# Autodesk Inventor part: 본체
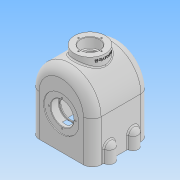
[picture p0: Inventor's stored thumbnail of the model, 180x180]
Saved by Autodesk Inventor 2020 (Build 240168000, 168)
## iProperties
Created: 2023-03
Part Number: 본체
Material: 일반
Document SubType Name: Modeling
Designer: user
Density: 1 g/cm^3
Appearance: 기본값
Author: user
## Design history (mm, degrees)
sketch "스케치1"
  geometry: L1 (-70, 94)-(70, 94); L2 (70, 94)-(70, 0); L3 (70, 0)-(-70, 0); L4 (-70, 0)-(-70, 94); L5 (-60, 94)-(-60, 0); L6 (60, 0)-(60, 94); A1 r 70 centre (0, 94) between (70, 94) and (-70, 94); A2 r 60 centre (0, 94) between (60, 94) and (-60, 94); 2 further points
  constraints: 12 end point, 4 point on circle, 3 parallel, 2 centre point, 2 midpoint, 2 point on line, 1 coincident, 1 horizontal, 1 perpendicular
  dimensions: "d1" = 94 distance of L3.end L1.start; "d2" = 140 distance of L2.end L3.end; "d3" = 10 radial gap between concentric circles of A1 A2; "d4" = 10 distance between parallel lines of L5 L4; "d5" = 10 distance between parallel lines of L2 L6
extrude "돌출1" new body sketch "스케치1" stored distance "d6" = 130; taper "d7" = 0 deg
sketch "스케치2"
  geometry: L1 (-60, 0)-(-60, 94) reference; L2 (60, 94)-(60, 0) reference; L3 (-70, 0)-(-70, 94) reference; L4 (70, 94)-(70, 0) reference; L5 (70, 0)-(60, 0) reference; L6 (60, 0)-(60, 94) reference; L7 (-60, 94)-(-60, 0) reference; L8 (-60, 0)-(-70, 0) reference; L9 (-60, 0)-(60, 0); A1 r 60 centre (0, 94) between (60, 94) and (-60, 94) reference; A2 r 70 centre (0, 94) between (70, 94) and (-70, 94) reference; A3 r 60 centre (0, 94) between (60, 94) and (-60, 94) reference; 1 further point
  constraints: 2 end point, 1 horizontal
extrude "돌출2" join sketch "스케치2" distance "d8" = 10; taper "d9" = 0 deg
sketch "스케치6"
  geometry: L1 (154, 55)-(0, 55) reference; L2 (0, 55)-(0, 65) reference; L3 (0, 65)-(164, 65) reference; L4 (164, 65)-(164, -65) reference; L5 (154, -55)-(154, 55) reference; L6 (164, -65)-(0, -65) reference; L7 (0, -65)-(0, -55) reference; L8 (0, -55)-(154, -55) reference; L9 (117, 65)-(117, 55); L10 (154, 55)-(94, 55) reference; L11 (117, 55)-(105.879, 43.879); L12 (103.757, 43)-(75, 43); L13 (75, 43)-(75, 65); L14 (75, 65)-(117, 65); A1 r 3 centre (103.757, 46) between (103.757, 43) and (105.879, 43.879); 3 further points
  constraints: 10 end point, 4 perpendicular, 4 point on line, 2 point on circle, 2 tangent, 1 centre point, 1 horizontal alignment
  dimensions: "d29" = 135 deg angle of L10 L11; "d30" = 22 distance of L12.end L13.end; "d50" = 75 distance of L2.end L13.end; "d51" = 60 diameter of point (105, 43) L13; "d52" = 3 radius of A1
revolve "회전3" sketch "스케치6" stored, may be unused: angle "d34" = 90 deg
sketch "스케치7"
  geometry: L1 (-70, 0)-(70, 0) reference; L2 (-70, 0)-(-70, 94) reference; L3 (70, 94)-(70, 0) reference; L4 (70, 0)-(-70, 0) reference; L5 (-70, 0)-(-70, 94) reference; L6 (70, 94)-(70, 0) reference; L7 (70, 0)-(-70, 0) reference; A1 r 70 centre (0, 94) between (70, 94) and (-70, 94) reference; A2 r 70 centre (0, 94) between (70, 94) and (-70, 94) reference; A3 r 70 centre (0, 94) between (70, 94) and (-70, 94) reference; 2 further points
  constraints: 1 vertical alignment
  dimensions: "d35" = 75 distance from line of L1 point (0, 75)
hole "구멍2" sketch "스케치7" at (0, 75) diameter "d36" = 52; stored, may be unused: countersink angle "d40" = 60 deg, drill point angle "d42" = 0 deg; dims "d37" = 6, "d38" = 80, "d39" = 2, "d41" = 18
sketch "스케치8"
  geometry: C1 r 26 at (0, 0) reference; 1 further point
hole "구멍3" sketch "스케치8" at (0, 0) diameter "d43" = 46; stored, may be unused: countersink angle "d47" = 60 deg, drill point angle "d49" = 0 deg; dims "d44" = 6, "d45" = 43, "d46" = 22, "d48" = 5
fillet "모깎기1" dims "d53" = 1
sketch "스케치9" dims "d54" = 60
  geometry: L1 (0, 0)-(0, 30); C1 r 26 at (0, 0) reference; 2 further points
  constraints: 2 coincident, 2 end point, 1 vertical, 1 vertical alignment, 2 other
hole "구멍4" sketch "스케치9" at (0, 30) diameter "d55" = 3.242; stored, may be unused: countersink angle "d59" = 60 deg, drill point angle "d61" = 118 deg; dims "d56" = 8, "d57" = 43, "d58" = 22, "d60" = 10
sketch "스케치12"
  geometry: L1 (140, 0)-(140, 130) reference; L2 (140, 104)-(140, 80); A1 r 12 centre (140, 92) between (140, 80) and (140, 104); 1 further point
  constraints: 3 point on line, 2 end point, 2 point on circle, 1 centre point
  dimensions: "d80" = 12 radius of A1; "d81" = 27 vertical distance of point (70, 65) A1.centre
extrude "돌출3" join sketch "스케치12" distance "d82" = 28; taper "d83" = 0 deg
node "작업 평면2"
sketch "스케치13"
  geometry: L1 (-70, 0)-(-70, 94) reference; L2 (70, 94)-(70, 28) reference; L3 (70, 28)-(82, 28) reference; L4 (82, 28)-(82, 0) reference; L5 (82, 0)-(60, 0) reference; L6 (60, 0)-(60, 94) reference; L7 (-60, 94)-(-60, 0) reference; L8 (-60, 0)-(-70, 0) reference; L9 (82, 28)-(70, 28) reference; L10 (70, 94)-(70, 0) reference; L11 (70, 40)-(70, 28); L12 (70, 28)-(82, 28); A1 r 60 centre (0, 94) between (60, 94) and (-60, 94) reference; A2 r 12 centre (70, 28) between (82, 28) and (70, 40); A3 r 70 centre (0, 94) between (70, 94) and (-70, 94) reference; 1 further point
  constraints: 4 end point, 2 point on circle, 1 centre point, 1 coincident, 1 collinear, 1 perpendicular, 1 point on line
revolve "회전4" sketch "스케치13" stored, may be unused: angle "d85" = 90 deg
sketch "스케치14"
  geometry: A1 r 12 centre (140, 92) between (140, 80) and (140, 104) reference; 1 further point
hole "구멍6" sketch "스케치14" at (140, 92) diameter "d86" = 10.106; stored, may be unused: countersink angle "d90" = 60 deg, drill point angle "d92" = 118 deg; dims "d87" = 24, "d88" = 43, "d89" = 22, "d91" = 26
fillet "모깎기2" dims "d93" = 20
fillet "모깎기3" dims "d94" = 3
node "작업 평면3"
sketch "스케치15"
  geometry: C1 r 35 at (0, 0); 1 further point
  constraints: 1 centre point, 1 coincident
  dimensions: "d96" = 70 diameter of C1
extrude "돌출4" join sketch "스케치15" stored distance "d97" = 28; taper "d98" = 0 deg
sketch "스케치16"
  geometry: C1 r 35 at (0, 0) reference
hole "구멍7" sketch "스케치16" at (0, 0) diameter "d99" = 34; stored, may be unused: countersink angle "d103" = 60 deg, drill point angle "d105" = 0 deg; dims "d100" = 24, "d101" = 43, "d102" = 22, "d104" = 26
sketch "스케치17" dims "d106" = 52
  geometry: L1 (0, 0)-(0, 26); C1 r 35 at (0, 0) reference; 1 further point
  constraints: 2 coincident, 2 end point, 1 vertical, 1 vertical alignment, 2 other
hole "구멍8" sketch "스케치17" at (0, 26) diameter "d107" = 3.242; stored, may be unused: countersink angle "d111" = 60 deg, drill point angle "d113" = 118 deg; dims "d108" = 8, "d109" = 43, "d110" = 22, "d112" = 10
fillet "모깎기4" dims "d117" = 3
chamfer "모따기1" distance "d118" = 1; stored, may be unused: second distance "d119" = 2, angle "d120" = 45 deg
fillet "모깎기5" dims "d121" = 10
node "작업 평면4"
sketch "스케치18"
  geometry: 1 further point
sketch "스케치19"
  geometry: L1 (1.739, 31.03)-(1.739, -31.03); L2 (1.739, -31.03)-(-17.739, -31.03); L3 (-17.739, -31.03)-(-17.739, 31.03); L4 (-17.739, 31.03)-(1.739, 31.03); L5 (-8, 31.03)-(-8, -31.03); L6 (-17.739, 0)-(1.739, 0); L7 (0, -35)-(0, 35) reference; 2 further points
  constraints: 5 midpoint, 4 end point, 1 horizontal alignment, 2 other
  dimensions: "d122" = 8 distance between parallel lines of L7 L5
feature "엠보싱2" sketch "스케치19" dims "d123" = 0.5, "d124" = 0
sketch "스케치20"
  geometry: L1 (100, 10)-(0, 10) reference; L2 (-10, 20)-(-10, 110) reference; L3 (100, 120)-(0, 120) reference; L4 (110, 20)-(110, 110) reference; A1 r 10 centre (0, 20) between (-10, 20) and (0, 10) reference; A2 r 10 centre (0, 110) between (0, 120) and (-10, 110) reference; A3 r 10 centre (100, 110) between (110, 110) and (100, 120) reference; A4 r 10 centre (100, 20) between (100, 10) and (110, 20) reference; 1 further point
extrude "돌출5" cut sketch "스케치20" distance "d125" = 50; taper "d126" = 0 deg
node "솔리드1"
mirror "미러1"
pattern_circular "원형 패턴1" dims angle "d63" = 360 deg
mirror "미러3"
mirror "미러4"
mirror "미러5"
pattern_circular "원형 패턴3" dims angle "d115" = 360 deg
node "절단 모서리 투영1"
node "절단 모서리 투영4"
node "절단 모서리 투영5"
node "절단 모서리 투영6"
node "절단 모서리 투영7"
feature "A9D066F2-1C7D-4E18-AEED-F7BC21143FA4" dims "d36" = 52, "d37" = 6, "d38" = 80, "d39" = 2, "d40" = 60 deg, "d41" = 18, "d42" = 0
other parameters: "d84" = 27, "d95" = 178
